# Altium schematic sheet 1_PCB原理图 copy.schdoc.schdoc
size 642 x 515 mm; Name: A_Customize; Symbol: A_Customize; Device: A_Customize; @Project Name: yu65; REV: 1.0; Date: 2022-11-27; Sheet: 1/1; Draw By: AMX1982; Company: Your Company; Convert to PCB: yes; Add into BOM: yes
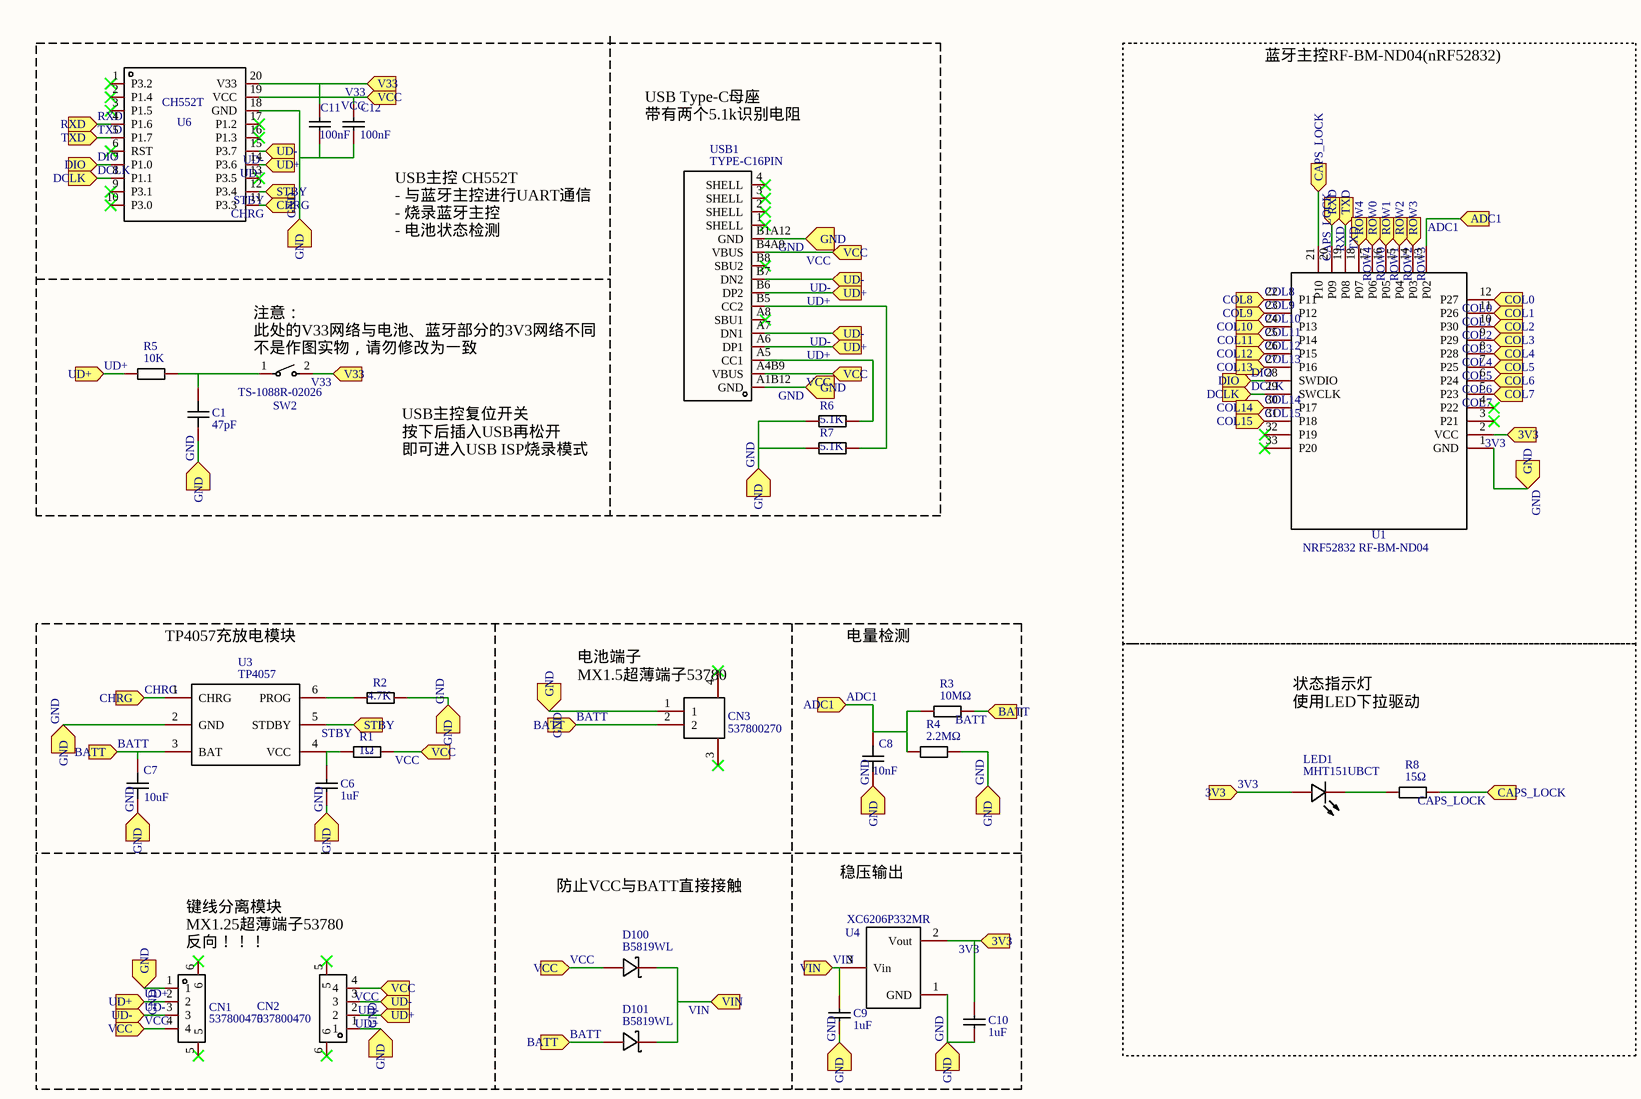
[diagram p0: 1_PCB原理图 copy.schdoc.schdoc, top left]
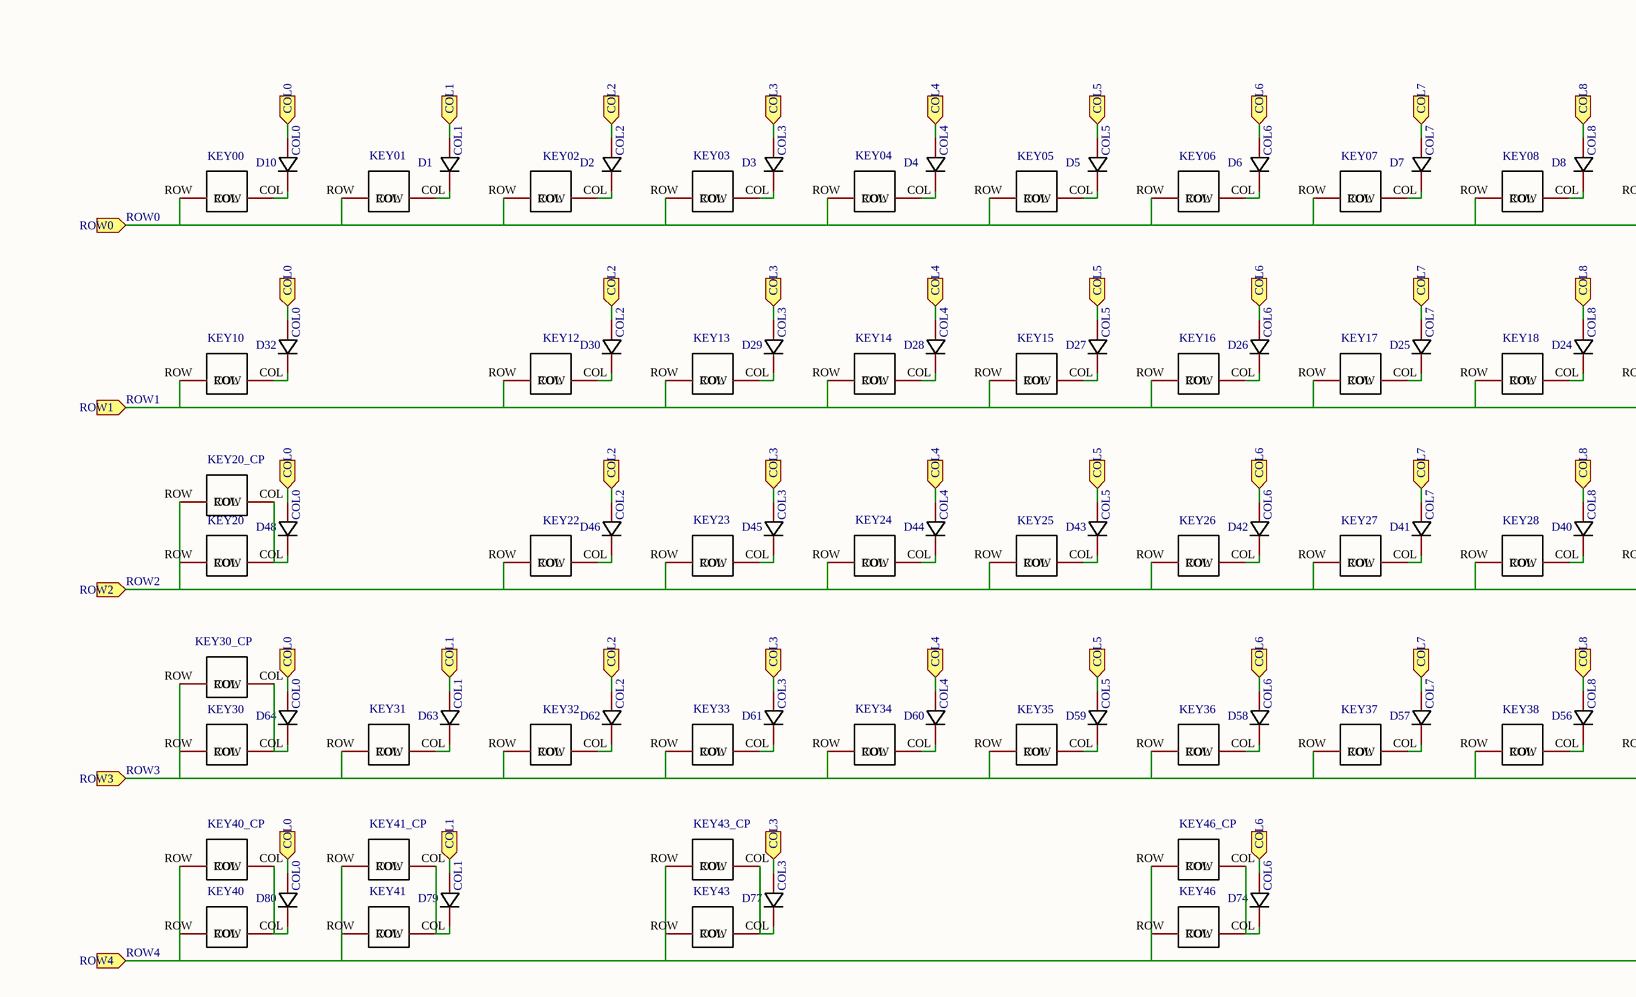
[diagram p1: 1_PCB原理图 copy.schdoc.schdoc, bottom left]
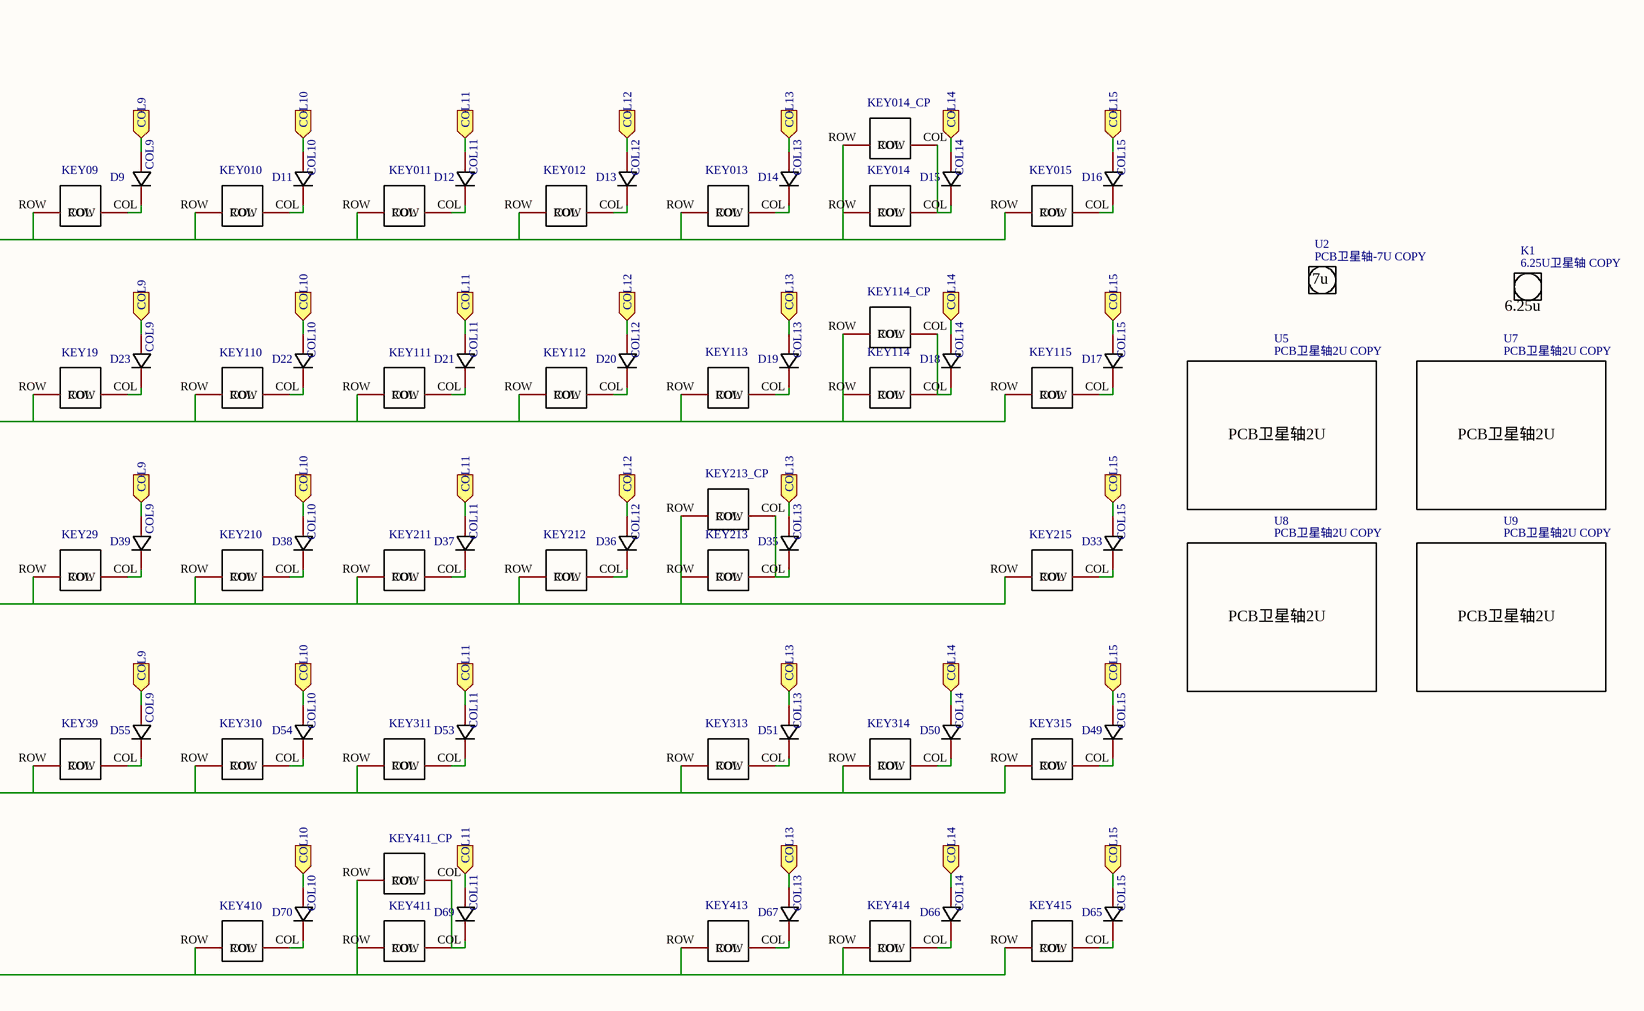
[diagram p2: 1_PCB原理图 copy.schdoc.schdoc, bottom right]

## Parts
C1  47pF  [C0805]
C6  1uF  [C0805]
C7  10uF  [C0805]
C8  10nF  [C0805]
C9  1uF  [C0805]
C10  1uF  [C0805]
C11  100nF  [C0805]
C12  100nF  [C0805]
CN1  537800470  [CONN-TH_4P-P1.25_537800470]
CN2  537800470  [CONN-TH_4P-P1.25_537800470]
CN3  537800270  [CONN-SMD_2P-P1.25_53780-0X70]
D1  1N4148W_C115103  [SOD-123_L2.8-W1.8-LS3.7-RD]  (value not drawn)
D2  1N4148W_C115103  [SOD-123_L2.8-W1.8-LS3.7-RD]  (value not drawn)
D3  1N4148W_C115103  [SOD-123_L2.8-W1.8-LS3.7-RD]  (value not drawn)
D4  1N4148W_C115103  [SOD-123_L2.8-W1.8-LS3.7-RD]  (value not drawn)
D5  1N4148W_C115103  [SOD-123_L2.8-W1.8-LS3.7-RD]  (value not drawn)
D6  1N4148W_C115103  [SOD-123_L2.8-W1.8-LS3.7-RD]  (value not drawn)
D7  1N4148W_C115103  [SOD-123_L2.8-W1.8-LS3.7-RD]  (value not drawn)
D8  1N4148W_C115103  [SOD-123_L2.8-W1.8-LS3.7-RD]  (value not drawn)
D9  1N4148W_C115103  [SOD-123_L2.8-W1.8-LS3.7-RD]  (value not drawn)
D10  1N4148W_C115103  [SOD-123_L2.8-W1.8-LS3.7-RD]  (value not drawn)
D11  1N4148W_C115103  [SOD-123_L2.8-W1.8-LS3.7-RD]  (value not drawn)
D12  1N4148W_C115103  [SOD-123_L2.8-W1.8-LS3.7-RD]  (value not drawn)
D13  1N4148W_C115103  [SOD-123_L2.8-W1.8-LS3.7-RD]  (value not drawn)
D14  1N4148W_C115103  [SOD-123_L2.8-W1.8-LS3.7-RD]  (value not drawn)
D15  1N4148W_C115103  [SOD-123_L2.8-W1.8-LS3.7-RD]  (value not drawn)
D16  1N4148W_C115103  [SOD-123_L2.8-W1.8-LS3.7-RD]  (value not drawn)
D17  1N4148W_C115103  [SOD-123_L2.8-W1.8-LS3.7-RD]  (value not drawn)
D18  1N4148W_C115103  [SOD-123_L2.8-W1.8-LS3.7-RD]  (value not drawn)
D19  1N4148W_C115103  [SOD-123_L2.8-W1.8-LS3.7-RD]  (value not drawn)
D20  1N4148W_C115103  [SOD-123_L2.8-W1.8-LS3.7-RD]  (value not drawn)
D21  1N4148W_C115103  [SOD-123_L2.8-W1.8-LS3.7-RD]  (value not drawn)
D22  1N4148W_C115103  [SOD-123_L2.8-W1.8-LS3.7-RD]  (value not drawn)
D23  1N4148W_C115103  [SOD-123_L2.8-W1.8-LS3.7-RD]  (value not drawn)
D24  1N4148W_C115103  [SOD-123_L2.8-W1.8-LS3.7-RD]  (value not drawn)
D25  1N4148W_C115103  [SOD-123_L2.8-W1.8-LS3.7-RD]  (value not drawn)
D26  1N4148W_C115103  [SOD-123_L2.8-W1.8-LS3.7-RD]  (value not drawn)
D27  1N4148W_C115103  [SOD-123_L2.8-W1.8-LS3.7-RD]  (value not drawn)
D28  1N4148W_C115103  [SOD-123_L2.8-W1.8-LS3.7-RD]  (value not drawn)
D29  1N4148W_C115103  [SOD-123_L2.8-W1.8-LS3.7-RD]  (value not drawn)
D30  1N4148W_C115103  [SOD-123_L2.8-W1.8-LS3.7-RD]  (value not drawn)
D32  1N4148W_C115103  [SOD-123_L2.8-W1.8-LS3.7-RD]  (value not drawn)
D33  1N4148W_C115103  [SOD-123_L2.8-W1.8-LS3.7-RD]  (value not drawn)
D35  1N4148W_C115103  [SOD-123_L2.8-W1.8-LS3.7-RD]  (value not drawn)
D36  1N4148W_C115103  [SOD-123_L2.8-W1.8-LS3.7-RD]  (value not drawn)
D37  1N4148W_C115103  [SOD-123_L2.8-W1.8-LS3.7-RD]  (value not drawn)
D38  1N4148W_C115103  [SOD-123_L2.8-W1.8-LS3.7-RD]  (value not drawn)
D39  1N4148W_C115103  [SOD-123_L2.8-W1.8-LS3.7-RD]  (value not drawn)
D40  1N4148W_C115103  [SOD-123_L2.8-W1.8-LS3.7-RD]  (value not drawn)
D41  1N4148W_C115103  [SOD-123_L2.8-W1.8-LS3.7-RD]  (value not drawn)
D42  1N4148W_C115103  [SOD-123_L2.8-W1.8-LS3.7-RD]  (value not drawn)
D43  1N4148W_C115103  [SOD-123_L2.8-W1.8-LS3.7-RD]  (value not drawn)
D44  1N4148W_C115103  [SOD-123_L2.8-W1.8-LS3.7-RD]  (value not drawn)
D45  1N4148W_C115103  [SOD-123_L2.8-W1.8-LS3.7-RD]  (value not drawn)
D46  1N4148W_C115103  [SOD-123_L2.8-W1.8-LS3.7-RD]  (value not drawn)
D48  1N4148W_C115103  [SOD-123_L2.8-W1.8-LS3.7-RD]  (value not drawn)
D49  1N4148W_C115103  [SOD-123_L2.8-W1.8-LS3.7-RD]  (value not drawn)
D50  1N4148W_C115103  [SOD-123_L2.8-W1.8-LS3.7-RD]  (value not drawn)
D51  1N4148W_C115103  [SOD-123_L2.8-W1.8-LS3.7-RD]  (value not drawn)
D53  1N4148W_C115103  [SOD-123_L2.8-W1.8-LS3.7-RD]  (value not drawn)
D54  1N4148W_C115103  [SOD-123_L2.8-W1.8-LS3.7-RD]  (value not drawn)
D55  1N4148W_C115103  [SOD-123_L2.8-W1.8-LS3.7-RD]  (value not drawn)
D56  1N4148W_C115103  [SOD-123_L2.8-W1.8-LS3.7-RD]  (value not drawn)
D57  1N4148W_C115103  [SOD-123_L2.8-W1.8-LS3.7-RD]  (value not drawn)
D58  1N4148W_C115103  [SOD-123_L2.8-W1.8-LS3.7-RD]  (value not drawn)
D59  1N4148W_C115103  [SOD-123_L2.8-W1.8-LS3.7-RD]  (value not drawn)
D60  1N4148W_C115103  [SOD-123_L2.8-W1.8-LS3.7-RD]  (value not drawn)
D61  1N4148W_C115103  [SOD-123_L2.8-W1.8-LS3.7-RD]  (value not drawn)
D62  1N4148W_C115103  [SOD-123_L2.8-W1.8-LS3.7-RD]  (value not drawn)
D63  1N4148W_C115103  [SOD-123_L2.8-W1.8-LS3.7-RD]  (value not drawn)
D64  1N4148W_C115103  [SOD-123_L2.8-W1.8-LS3.7-RD]  (value not drawn)
D65  1N4148W_C115103  [SOD-123_L2.8-W1.8-LS3.7-RD]  (value not drawn)
D66  1N4148W_C115103  [SOD-123_L2.8-W1.8-LS3.7-RD]  (value not drawn)
D67  1N4148W_C115103  [SOD-123_L2.8-W1.8-LS3.7-RD]  (value not drawn)
D69  1N4148W_C115103  [SOD-123_L2.8-W1.8-LS3.7-RD]  (value not drawn)
D70  1N4148W_C115103  [SOD-123_L2.8-W1.8-LS3.7-RD]  (value not drawn)
D74  1N4148W_C115103  [SOD-123_L2.8-W1.8-LS3.7-RD]  (value not drawn)
D77  1N4148W_C115103  [SOD-123_L2.8-W1.8-LS3.7-RD]  (value not drawn)
D79  1N4148W_C115103  [SOD-123_L2.8-W1.8-LS3.7-RD]  (value not drawn)
D80  1N4148W_C115103  [SOD-123_L2.8-W1.8-LS3.7-RD]  (value not drawn)
D100  B5819WL  [SOD-123F_L2.8-W1.8-LS3.7-RD]
D101  B5819WL  [SOD-123F_L2.8-W1.8-LS3.7-RD]
K1  6.25U卫星轴 COPY  [6.25U卫星轴]
KEY00  KEY00  [凯华轴座无灯]  (value not drawn)
KEY01  KEY01  [凯华轴座无灯]  (value not drawn)
KEY02  凯华轴座无灯 COPY  [凯华轴座无灯]  (value not drawn)
KEY03  凯华轴座无灯 COPY  [凯华轴座无灯]  (value not drawn)
KEY04  凯华轴座无灯 COPY  [凯华轴座无灯]  (value not drawn)
KEY05  凯华轴座无灯 COPY  [凯华轴座无灯]  (value not drawn)
KEY06  凯华轴座无灯 COPY  [凯华轴座无灯]  (value not drawn)
KEY07  凯华轴座无灯 COPY  [凯华轴座无灯]  (value not drawn)
KEY08  凯华轴座无灯 COPY  [凯华轴座无灯]  (value not drawn)
KEY09  凯华轴座无灯 COPY  [凯华轴座无灯]  (value not drawn)
KEY010  凯华轴座无灯 COPY  [凯华轴座无灯]  (value not drawn)
KEY10  KEY00  [凯华轴座无灯]  (value not drawn)
KEY011  凯华轴座无灯 COPY  [凯华轴座无灯]  (value not drawn)
KEY012  凯华轴座无灯 COPY  [凯华轴座无灯]  (value not drawn)
KEY12  凯华轴座无灯 COPY  [凯华轴座无灯]  (value not drawn)
KEY013  凯华轴座无灯 COPY  [凯华轴座无灯]  (value not drawn)
KEY13  凯华轴座无灯 COPY  [凯华轴座无灯]  (value not drawn)
KEY014  凯华轴座无灯 COPY  [凯华轴座无灯]  (value not drawn)
KEY14  凯华轴座无灯 COPY  [凯华轴座无灯]  (value not drawn)
KEY014_CP  凯华轴座无灯 COPY  [凯华轴座无灯]  (value not drawn)
KEY015  凯华轴座无灯 COPY  [凯华轴座无灯]  (value not drawn)
KEY15  凯华轴座无灯 COPY  [凯华轴座无灯]  (value not drawn)
KEY16  凯华轴座无灯 COPY  [凯华轴座无灯]  (value not drawn)
KEY17  凯华轴座无灯 COPY  [凯华轴座无灯]  (value not drawn)
KEY18  凯华轴座无灯 COPY  [凯华轴座无灯]  (value not drawn)
KEY19  凯华轴座无灯 COPY  [凯华轴座无灯]  (value not drawn)
KEY20  KEY00  [凯华轴座无灯]  (value not drawn)
KEY20_CP  KEY00  [凯华轴座无灯]  (value not drawn)
KEY22  凯华轴座无灯 COPY  [凯华轴座无灯]  (value not drawn)
KEY23  凯华轴座无灯 COPY  [凯华轴座无灯]  (value not drawn)
KEY24  凯华轴座无灯 COPY  [凯华轴座无灯]  (value not drawn)
KEY25  凯华轴座无灯 COPY  [凯华轴座无灯]  (value not drawn)
KEY26  凯华轴座无灯 COPY  [凯华轴座无灯]  (value not drawn)
KEY27  凯华轴座无灯 COPY  [凯华轴座无灯]  (value not drawn)
KEY28  凯华轴座无灯 COPY  [凯华轴座无灯]  (value not drawn)
KEY29  凯华轴座无灯 COPY  [凯华轴座无灯]  (value not drawn)
KEY30  KEY00  [凯华轴座无灯]  (value not drawn)
KEY30_CP  KEY00  [凯华轴座无灯]  (value not drawn)
KEY31  KEY01  [凯华轴座无灯]  (value not drawn)
KEY32  凯华轴座无灯 COPY  [凯华轴座无灯]  (value not drawn)
KEY33  凯华轴座无灯 COPY  [凯华轴座无灯]  (value not drawn)
KEY34  凯华轴座无灯 COPY  [凯华轴座无灯]  (value not drawn)
KEY35  凯华轴座无灯 COPY  [凯华轴座无灯]  (value not drawn)
KEY36  凯华轴座无灯 COPY  [凯华轴座无灯]  (value not drawn)
KEY37  凯华轴座无灯 COPY  [凯华轴座无灯]  (value not drawn)
KEY38  凯华轴座无灯 COPY  [凯华轴座无灯]  (value not drawn)
KEY39  凯华轴座无灯 COPY  [凯华轴座无灯]  (value not drawn)
KEY40  KEY00  [凯华轴座无灯]  (value not drawn)
KEY40_CP  KEY00  [凯华轴座无灯]  (value not drawn)
KEY41  KEY01  [凯华轴座无灯]  (value not drawn)
KEY41_CP  KEY01  [凯华轴座无灯]  (value not drawn)
KEY43  凯华轴座无灯 COPY  [凯华轴座无灯]  (value not drawn)
KEY43_CP  凯华轴座无灯 COPY  [凯华轴座无灯]  (value not drawn)
KEY46  凯华轴座无灯 COPY  [凯华轴座无灯]  (value not drawn)
KEY46_CP  凯华轴座无灯 COPY  [凯华轴座无灯]  (value not drawn)
KEY110  凯华轴座无灯 COPY  [凯华轴座无灯]  (value not drawn)
KEY111  凯华轴座无灯 COPY  [凯华轴座无灯]  (value not drawn)
KEY112  凯华轴座无灯 COPY  [凯华轴座无灯]  (value not drawn)
KEY113  凯华轴座无灯 COPY  [凯华轴座无灯]  (value not drawn)
KEY114  凯华轴座无灯 COPY  [凯华轴座无灯]  (value not drawn)
KEY114_CP  凯华轴座无灯 COPY  [凯华轴座无灯]  (value not drawn)
KEY115  凯华轴座无灯 COPY  [凯华轴座无灯]  (value not drawn)
KEY210  凯华轴座无灯 COPY  [凯华轴座无灯]  (value not drawn)
KEY211  凯华轴座无灯 COPY  [凯华轴座无灯]  (value not drawn)
KEY212  凯华轴座无灯 COPY  [凯华轴座无灯]  (value not drawn)
KEY213  凯华轴座无灯 COPY  [凯华轴座无灯]  (value not drawn)
KEY213_CP  凯华轴座无灯 COPY  [凯华轴座无灯]  (value not drawn)
KEY215  凯华轴座无灯 COPY  [凯华轴座无灯]  (value not drawn)
KEY310  凯华轴座无灯 COPY  [凯华轴座无灯]  (value not drawn)
KEY311  凯华轴座无灯 COPY  [凯华轴座无灯]  (value not drawn)
KEY313  凯华轴座无灯 COPY  [凯华轴座无灯]  (value not drawn)
KEY314  凯华轴座无灯 COPY  [凯华轴座无灯]  (value not drawn)
KEY315  凯华轴座无灯 COPY  [凯华轴座无灯]  (value not drawn)
KEY410  凯华轴座无灯 COPY  [凯华轴座无灯]  (value not drawn)
KEY411  凯华轴座无灯 COPY  [凯华轴座无灯]  (value not drawn)
KEY411_CP  凯华轴座无灯 COPY  [凯华轴座无灯]  (value not drawn)
KEY413  凯华轴座无灯 COPY  [凯华轴座无灯]  (value not drawn)
KEY414  凯华轴座无灯 COPY  [凯华轴座无灯]  (value not drawn)
KEY415  凯华轴座无灯 COPY  [凯华轴座无灯]  (value not drawn)
LED1  MHT151UBCT  [LED-SMD_L3.2-W1.3-RD-EH2.1]
R1  1Ω  [R0805]
R2  4.7K  [R0805]
R3  10MΩ  [R0805]
R4  2.2MΩ  [R0805]
R5  10K  [R0805]
R6  5.1K  [R0805]
R7  5.1K  [R0805]
R8  15Ω  [R0805]
SW2  TS-1088R-02026  [SW-SMD_L3.9-W3.0-P4.45]
U1  NRF52832 RF-BM-ND04  [BULETM-SMD_NRF52832]
U2  PCB卫星轴-7U COPY  [PCB卫星轴-7U]
U3  TP4057  [SOT-23-6_L2.9-W1.6-P0.95-LS2.8-BR]
U4  XC6206P332MR  [SOT-23-3_L2.9-W1.6-P1.90-LS2.8-BR]
U5  PCB卫星轴2U COPY  [卫星轴2U]
U6  CH552T  [TSSOP-20_L6.5-W4.4-P0.65-LS6.4-BL]
U7  PCB卫星轴2U COPY  [卫星轴2U]
U8  PCB卫星轴2U COPY  [卫星轴2U]
U9  PCB卫星轴2U COPY  [卫星轴2U]
USB1  TYPE-C16PIN  [USB-C-SMD_TYPE-C-6PIN-2MD-073]

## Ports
3V3 (in), ADC1 (in), BATT (in), CAPS_LOCK (in), CHRG (in), COL0 (in), COL1 (in), COL2 (in), COL3 (in), COL4 (in), COL5 (in), COL6 (in), COL7 (in), COL8 (in), COL9 (in), COL10 (in), COL11 (in), COL12 (in), COL13 (in), COL14 (in), COL15 (in), DCLK (in), DIO (in), GND (in), ROW0 (in), ROW1 (in), ROW2 (in), ROW3 (in), ROW4 (in), RXD (in), STBY (in), TXD (in), UD+ (in), UD- (in), V33 (in), VCC (in), VIN (in)

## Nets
3V3: C10.2 LED1.1(+) U1.2(VCC) U4.2(Vout) ; port 3V3
ADC1: C8.1 R3.1 R4.1 U1.13(P02) ; port ADC1
BATT: C7.2 CN3.2 D101.2(A) R3.2 U3.3(BAT) ; port BATT
CAPS_LOCK: R8.2 U1.21(P10) ; port CAPS_LOCK
CHRG: U3.1(CHRG) U6.11(P3.3) ; port CHRG
COL0: D10.2(A) D32.2(A) D48.2(A) D64.2(A) D80.2(A) U1.12(P27) ; port COL0
COL1: D1.2(A) D63.2(A) D79.2(A) U1.11(P26) ; port COL1
COL2: D2.2(A) D30.2(A) D46.2(A) D62.2(A) U1.10(P30) ; port COL2
COL3: D3.2(A) D29.2(A) D45.2(A) D61.2(A) D77.2(A) U1.9(P29) ; port COL3
COL4: D4.2(A) D28.2(A) D44.2(A) D60.2(A) U1.8(P28) ; port COL4
COL5: D5.2(A) D27.2(A) D43.2(A) D59.2(A) U1.7(P25) ; port COL5
COL6: D6.2(A) D26.2(A) D42.2(A) D58.2(A) D74.2(A) U1.6(P24) ; port COL6
COL7: D7.2(A) D25.2(A) D41.2(A) D57.2(A) U1.5(P23) ; port COL7
COL8: D8.2(A) D24.2(A) D40.2(A) D56.2(A) U1.22(P11) ; port COL8
COL9: D9.2(A) D23.2(A) D39.2(A) D55.2(A) U1.23(P12) ; port COL9
COL10: D11.2(A) D22.2(A) D38.2(A) D54.2(A) D70.2(A) U1.24(P13) ; port COL10
COL11: D12.2(A) D21.2(A) D37.2(A) D53.2(A) D69.2(A) U1.25(P14) ; port COL11
COL12: D13.2(A) D20.2(A) D36.2(A) U1.26(P15) ; port COL12
COL13: D14.2(A) D19.2(A) D35.2(A) D51.2(A) D67.2(A) U1.27(P16) ; port COL13
COL14: D15.2(A) D18.2(A) D50.2(A) D66.2(A) U1.30(P17) ; port COL14
COL15: D16.2(A) D17.2(A) D33.2(A) D49.2(A) D65.2(A) U1.31(P18) ; port COL15
DCLK: U1.29(SWCLK) U6.8(P1.1) ; port DCLK
DIO: U1.28(SWDIO) U6.7(P1.0) ; port DIO
GND: C1.1 C6.1 C7.1 C8.2 C9.1 C10.1 C11.1 C12.1 CN1.1 CN2.1 CN3.1 R2.2 R4.2 R6.1 R7.1 U1.1(GND) U3.2(GND) U4.1(GND) U6.18(GND) USB1.A1B12(GND) USB1.B1A12(GND) ; port GND
ROW0: KEY00.ROW KEY01.ROW KEY02.ROW KEY03.ROW KEY04.ROW KEY05.ROW KEY06.ROW KEY07.ROW KEY08.ROW KEY09.ROW KEY010.ROW KEY011.ROW KEY012.ROW KEY013.ROW KEY014.ROW KEY014_CP.ROW KEY015.ROW U1.17(P06) ; port ROW0
ROW1: KEY10.ROW KEY12.ROW KEY13.ROW KEY14.ROW KEY15.ROW KEY16.ROW KEY17.ROW KEY18.ROW KEY19.ROW KEY110.ROW KEY111.ROW KEY112.ROW KEY113.ROW KEY114.ROW KEY114_CP.ROW KEY115.ROW U1.16(P05) ; port ROW1
ROW2: KEY20.ROW KEY20_CP.ROW KEY22.ROW KEY23.ROW KEY24.ROW KEY25.ROW KEY26.ROW KEY27.ROW KEY28.ROW KEY29.ROW KEY210.ROW KEY211.ROW KEY212.ROW KEY213.ROW KEY213_CP.ROW KEY215.ROW U1.15(P04) ; port ROW2
ROW3: KEY30.ROW KEY30_CP.ROW KEY31.ROW KEY32.ROW KEY33.ROW KEY34.ROW KEY35.ROW KEY36.ROW KEY37.ROW KEY38.ROW KEY39.ROW KEY310.ROW KEY311.ROW KEY313.ROW KEY314.ROW KEY315.ROW U1.14(P03) ; port ROW3
ROW4: KEY40.ROW KEY40_CP.ROW KEY41.ROW KEY41_CP.ROW KEY43.ROW KEY43_CP.ROW KEY46.ROW KEY46_CP.ROW KEY410.ROW KEY411.ROW KEY411_CP.ROW KEY413.ROW KEY414.ROW KEY415.ROW U1.18(P07) ; port ROW4
RXD: U1.20(P09) U6.4(P1.6) ; port RXD
STBY: U3.5(STDBY) U6.12(P3.4) ; port STBY
TXD: U1.19(P08) U6.5(P1.7) ; port TXD
UD+: CN1.2 CN2.2 R5.1 U6.14(P3.6) USB1.A6(DP1) USB1.B6(DP2) ; port UD+
UD-: CN1.3 CN2.3 U6.15(P3.7) USB1.A7(DN1) USB1.B7(DN2) ; port UD-
V33: C11.2 SW2.2 U6.20(V33) ; port V33
VCC: C12.2 CN1.4 CN2.4 D100.2(A) R1.2 U6.19(VCC) USB1.A4B9(VBUS) USB1.B4A9(VBUS) ; port VCC
VIN: C9.2 D100.1(K) D101.1(K) U4.3(Vin) ; port VIN
NetC1_2: C1.2 R5.2 SW2.1
NetC6_2: C6.2 R1.1 U3.4(VCC)
NetD1_1: D1.1(K) KEY01.COL
NetD2_1: D2.1(K) KEY02.COL
NetD3_1: D3.1(K) KEY03.COL
NetD4_1: D4.1(K) KEY04.COL
NetD5_1: D5.1(K) KEY05.COL
NetD6_1: D6.1(K) KEY06.COL
NetD7_1: D7.1(K) KEY07.COL
NetD8_1: D8.1(K) KEY08.COL
NetD9_1: D9.1(K) KEY09.COL
NetD10_1: D10.1(K) KEY00.COL
NetD11_1: D11.1(K) KEY010.COL
NetD12_1: D12.1(K) KEY011.COL
NetD13_1: D13.1(K) KEY012.COL
NetD14_1: D14.1(K) KEY013.COL
NetD15_1: D15.1(K) KEY014.COL KEY014_CP.COL
NetD16_1: D16.1(K) KEY015.COL
NetD17_1: D17.1(K) KEY115.COL
NetD18_1: D18.1(K) KEY114.COL KEY114_CP.COL
NetD19_1: D19.1(K) KEY113.COL
NetD20_1: D20.1(K) KEY112.COL
NetD21_1: D21.1(K) KEY111.COL
NetD22_1: D22.1(K) KEY110.COL
NetD23_1: D23.1(K) KEY19.COL
NetD24_1: D24.1(K) KEY18.COL
NetD25_1: D25.1(K) KEY17.COL
NetD26_1: D26.1(K) KEY16.COL
NetD27_1: D27.1(K) KEY15.COL
NetD28_1: D28.1(K) KEY14.COL
NetD29_1: D29.1(K) KEY13.COL
NetD30_1: D30.1(K) KEY12.COL
NetD32_1: D32.1(K) KEY10.COL
NetD33_1: D33.1(K) KEY215.COL
NetD35_1: D35.1(K) KEY213.COL KEY213_CP.COL
NetD36_1: D36.1(K) KEY212.COL
NetD37_1: D37.1(K) KEY211.COL
NetD38_1: D38.1(K) KEY210.COL
NetD39_1: D39.1(K) KEY29.COL
NetD40_1: D40.1(K) KEY28.COL
NetD41_1: D41.1(K) KEY27.COL
NetD42_1: D42.1(K) KEY26.COL
NetD43_1: D43.1(K) KEY25.COL
NetD44_1: D44.1(K) KEY24.COL
NetD45_1: D45.1(K) KEY23.COL
NetD46_1: D46.1(K) KEY22.COL
NetD48_1: D48.1(K) KEY20.COL KEY20_CP.COL
NetD49_1: D49.1(K) KEY315.COL
NetD50_1: D50.1(K) KEY314.COL
NetD51_1: D51.1(K) KEY313.COL
NetD53_1: D53.1(K) KEY311.COL
NetD54_1: D54.1(K) KEY310.COL
NetD55_1: D55.1(K) KEY39.COL
NetD56_1: D56.1(K) KEY38.COL
NetD57_1: D57.1(K) KEY37.COL
NetD58_1: D58.1(K) KEY36.COL
NetD59_1: D59.1(K) KEY35.COL
NetD60_1: D60.1(K) KEY34.COL
NetD61_1: D61.1(K) KEY33.COL
NetD62_1: D62.1(K) KEY32.COL
NetD63_1: D63.1(K) KEY31.COL
NetD64_1: D64.1(K) KEY30.COL KEY30_CP.COL
NetD65_1: D65.1(K) KEY415.COL
NetD66_1: D66.1(K) KEY414.COL
NetD67_1: D67.1(K) KEY413.COL
NetD69_1: D69.1(K) KEY411.COL KEY411_CP.COL
NetD70_1: D70.1(K) KEY410.COL
NetD74_1: D74.1(K) KEY46.COL KEY46_CP.COL
NetD77_1: D77.1(K) KEY43.COL KEY43_CP.COL
NetD79_1: D79.1(K) KEY41.COL KEY41_CP.COL
NetD80_1: D80.1(K) KEY40.COL KEY40_CP.COL
NetLED1_2: LED1.2(-) R8.1
NetR2_1: R2.1 U3.6(PROG)
NetR6_2: R6.2 USB1.A5(CC1)
NetR7_2: R7.2 USB1.B5(CC2)

Not connected (* = marked no-connect by the designer): CN1 5* 6*; CN2 5* 6*; CN3 3* 4*; U1 3(P21)* 4(P22)* 32(P19)* 33(P20)*; U6 1(P3.2)* 2(P1.4)* 3(P1.5)* 6(RST)* 9(P3.1)* 10(P3.0)* 13(P3.5)* 16(P1.3)* 17(P1.2)*; USB1 1(SHELL)* 2(SHELL)* 3(SHELL)* 4(SHELL)* A8(SBU1)* B8(SBU2)*

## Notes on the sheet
- (near USB1) USB Type-C母座
  带有两个5.1k识别电阻
- 蓝牙主控RF-BM-ND04(nRF52832)
- USB主控 CH552T
  - 与蓝牙主控进行UART通信
  - 烧录蓝牙主控
  - 电池状态检测
- (near SW2) 注意：
  此处的V33网络与电池、蓝牙部分的3V3网络不同
  不是作图实物，请勿修改为一致
- USB主控复位开关
  按下后插入USB再松开
  即可进入USB ISP烧录模式
- (near U3) TP4057充放电模块
- (near CN3) 电池端子
  MX1.5超薄端子53780
- 电量检测
- 状态指示灯
  使用LED下拉驱动
- (near CN1) 键线分离模块
  MX1.25超薄端子53780
  反向！！！
- 防止VCC与BATT直接接触
- 稳压输出

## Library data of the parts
C1 = 47pF: Manufacturer: YAGEO(国巨); Manufacturer Part: AC0805JRNPO9BN470; Convert to PCB: yes
C6 C9 C10 = 1uF: Manufacturer: FH(风华); Manufacturer Part: 0805F105M500NT; Convert to PCB: yes
C7 = 10uF: Manufacturer: FH; Manufacturer Part: 0805X106K100NT; Convert to PCB: yes
C8 = 10nF: Manufacturer: MuRata; Manufacturer Part: GRM216R71H103KA01D; Convert to PCB: yes
C11 C12 = 100nF: Manufacturer Part: CL21B104JBCNNNC; Manufacturer: SAMSUNG; Convert to PCB: yes
CN1 CN2 = 537800470: Manufacturer: MOLEX; Convert to PCB: yes
CN3 = 537800270: Manufacturer: MOLEX; Convert to PCB: yes
D1-D30 D32 D33 D35-D46 D48-D51 D53-D67 D69 D70 D74 D77 D79 D80 = 1N4148W_C115103: Manufacturer: Jingdao; Convert to PCB: yes
D100 D101 = B5819WL: Manufacturer: SK; Convert to PCB: yes
K1 = 6.25U卫星轴 COPY: Manufacturer Part: Cherry MX; Convert to PCB: yes
KEY00 KEY10 KEY20 KEY20_CP KEY30 KEY30_CP KEY40 KEY40_CP = KEY00: Convert to PCB: yes
KEY01 KEY31 KEY41 KEY41_CP = KEY01: Convert to PCB: yes
KEY02 KEY03 KEY04 KEY05 KEY06 KEY07 KEY08 KEY09 KEY010 KEY011 KEY012 KEY12 KEY013 KEY13 KEY014 KEY14 KEY014_CP KEY015 KEY15-KEY19 KEY22-KEY29 KEY32-KEY39 KEY43 KEY43_CP KEY46 KEY46_CP KEY110-KEY114 KEY114_CP KEY115 KEY210-KEY213 KEY213_CP KEY215 KEY310 KEY311 KEY313-KEY315 KEY410 KEY411 KEY411_CP KEY413-KEY415 = 凯华轴座无灯 COPY: Convert to PCB: yes
LED1 = MHT151UBCT: Manufacturer: MEIHUA(美华); Convert to PCB: yes
R1 = 1Ω: Manufacturer: UNI-ROYAL(厚声); Manufacturer Part: 0805W8F100KT5E; Convert to PCB: yes
R2 = 4.7K: Manufacturer: Tyohm; Manufacturer Part: RMC08054.7K5%N; Convert to PCB: yes
R3 = 10MΩ: Manufacturer: YAGEO(国巨); Manufacturer Part: RC0805FR-0710ML; Convert to PCB: yes
R4 = 2.2MΩ: Manufacturer: YAGEO(国巨); Manufacturer Part: RC0805FR-072M2L; Convert to PCB: yes
R5 = 10K: Manufacturer: Ever Ohms Tech; Manufacturer Part: TR0805D10KP0550; Convert to PCB: yes
R6 R7 = 5.1K: Manufacturer: Tyohm; Manufacturer Part: RMC08055.1K1%N; Convert to PCB: yes
R8 = 15Ω: Manufacturer: YAGEO(国巨); Manufacturer Part: RC0805JR-0715RL; Convert to PCB: yes
SW2 = TS-1088R-02026: Manufacturer: XUNPU; Convert to PCB: yes
U1 = NRF52832 RF-BM-ND04: Convert to PCB: yes
U2 = PCB卫星轴-7U COPY: Convert to PCB: yes
U3 = TP4057: Manufacturer: TOPPOWER; Convert to PCB: yes
U4 = XC6206P332MR: Manufacturer: TOREX; Convert to PCB: yes
U5 U7-U9 = PCB卫星轴2U COPY: Convert to PCB: yes
U6 = CH552T: Manufacturer: WCH; Convert to PCB: yes
USB1 = TYPE-C16PIN: Manufacturer: SHOU HAN; Convert to PCB: yes; Origin Footprint: USB-C-SMD_TYPE-C16PIN-SHOUHAN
